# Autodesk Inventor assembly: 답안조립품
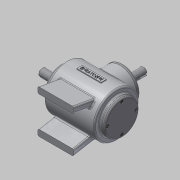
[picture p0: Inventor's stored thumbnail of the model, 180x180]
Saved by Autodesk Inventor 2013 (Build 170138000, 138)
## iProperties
Created: 2015-01
Part Number: 답안조립품
Document SubType Name: Assembly
Designer: Administrator
Author: Administrator
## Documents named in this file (15)
- C:\Users\Administrator\Desktop\450106V1004\답안조립품.iam
- C:\Users\Administrator\Desktop\450106V1004\1 본체.ipt
- C:\Users\Administrator\Desktop\450106V1004\커버.ipt
- C:\Users\Administrator\Desktop\450106V1004\M4.ipt
- C:\Users\Administrator\Desktop\450106V1004\커버2.ipt
- C:\Users\Administrator\Desktop\450106V1004\오일실.ipt
- C:\Users\Administrator\Desktop\450106V1004\베어링 6203.ipt
- C:\Users\Administrator\Desktop\450106V1004\메인 축.ipt
- 메인 축.ipt
- C:\Users\Administrator\Desktop\450106V1004\키 5x5.ipt
- C:\Users\Administrator\Desktop\450106V1004\메인 베벨기어.ipt
- C:\Users\Administrator\Desktop\450106V1004\서브 축.ipt
- 서브 축.ipt
- C:\Users\Administrator\Desktop\450106V1004\키 4x4.ipt
- C:\Users\Administrator\Desktop\450106V1004\서브 베벨기어.ipt
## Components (13 placed, 2 different names)
1. 1 본체:1
2. M4:1
3. M4:3
4. M4:4
5. M4:5
6. M4:2
7. M4:6
8. M4:7
9. M4:8
10. M4:9
11. M4:10
12. M4:11
13. M4:12
